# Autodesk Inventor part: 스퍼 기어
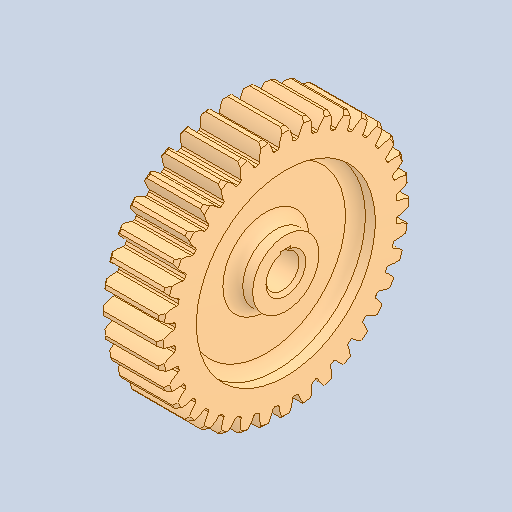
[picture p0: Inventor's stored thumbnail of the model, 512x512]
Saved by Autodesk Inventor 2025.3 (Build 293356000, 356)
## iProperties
Created: 2025-10
Part Number: 스퍼 기어
Material: 강철, 합금
Document SubType Name: Modeling
Designer: USER
Density: 7.73 g/cm^3
Appearance: 기본값
Author: jhkim
Sending System: Autodesk Inventor 2026
Preprocessor: ST-DEVELOPER v20.1
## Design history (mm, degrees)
feature "솔리드1"
node "솔리드2"
